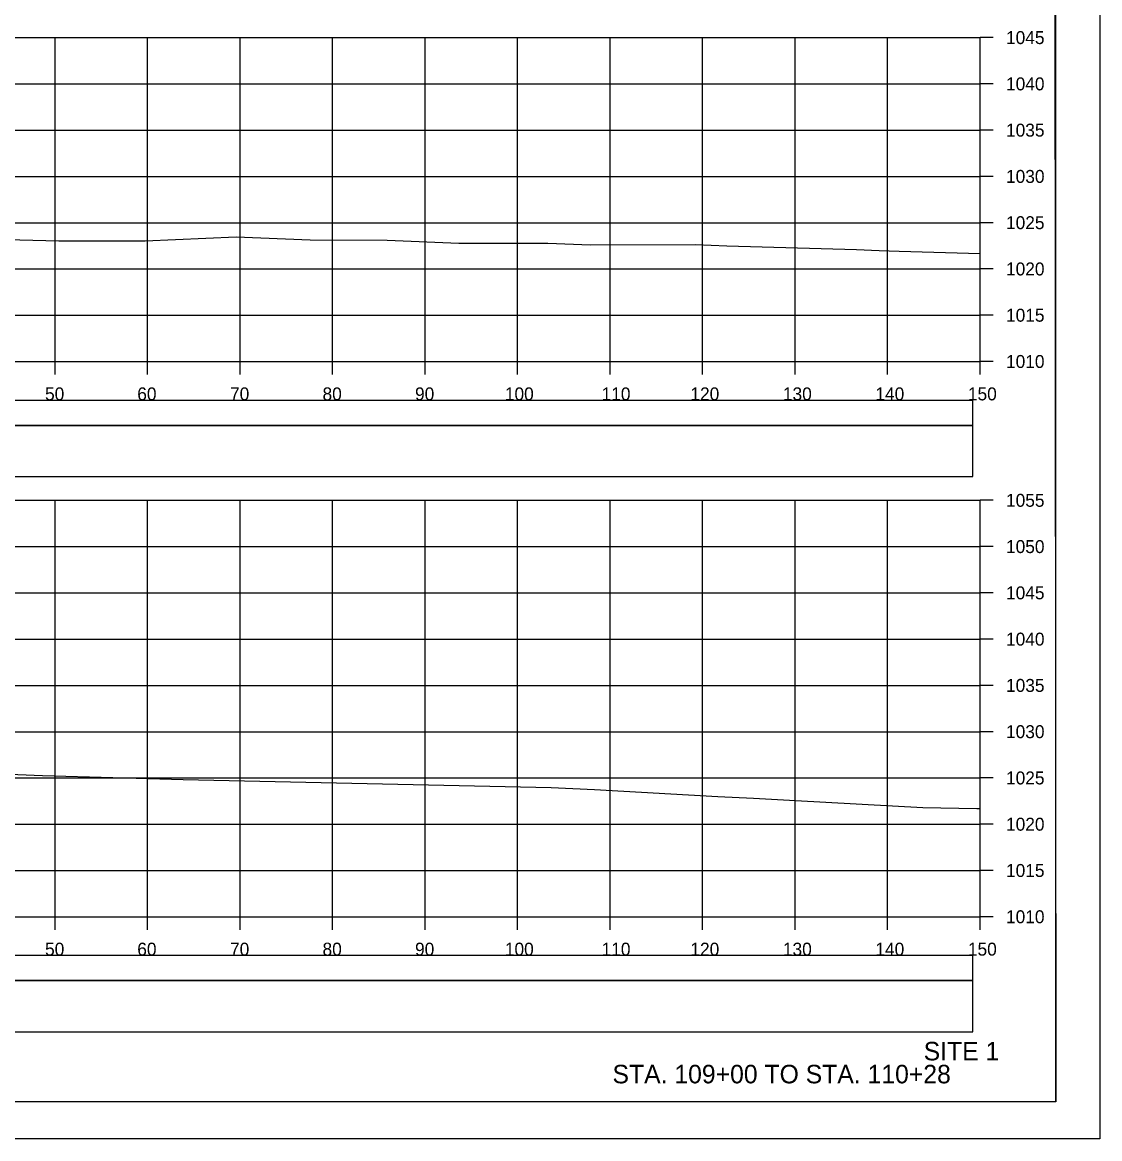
# Model space of a CAD drawing. Extents: x 1370565 to 1374448, y 301010 to 304637.
# Drawn here: x 1370781.5 to 1370898, y 302290.5 to 302411.2 of the extents above; entities that cross this region are included whole.
import ezdxf

# ---------------------------------------------------------------- set-up
doc = ezdxf.new("R2010")
doc.units = 0
for name, color, linetype in [('R_Axis', 7, 'Continuous'), ('R_Axis Annot', 7, 'Continuous'), ('R_Border', 7, 'Continuous'), ('R_Draft', 7, 'Continuous'), ('R_Drive', 7, 'Continuous'), ('R_Exist Surface', 7, 'Continuous'), ('R_Grid', 7, 'Continuous'), ('R_No Plot', 7, 'Continuous')]:
    doc.layers.add(name, color=color, linetype=linetype)

msp = doc.modelspace()

# ---------------------------------------------------------------- linework, layer by layer
at = {"layer": 'R_Axis'}
for p, q in [((1370885.03, 302374.5), (1370885.03, 302409.5)), ((1370886.43, 302409.5), (1370885.03, 302409.5)), ((1370886.43, 302404.5), (1370885.03, 302404.5)), ((1370886.43, 302399.5), (1370885.03, 302399.5)), ((1370886.43, 302394.5), (1370885.03, 302394.5)), ((1370886.43, 302389.5), (1370885.03, 302389.5)), ((1370886.43, 302384.5), (1370885.03, 302384.5)), ((1370886.43, 302379.5), (1370885.03, 302379.5)), ((1370585.03, 302374.5), (1370885.03, 302374.5)), ((1370785.03, 302373.1), (1370785.03, 302374.5)), ((1370795.03, 302373.1), (1370795.03, 302374.5)), ((1370805.03, 302373.1), (1370805.03, 302374.5)), ((1370815.03, 302373.1), (1370815.03, 302374.5)), ((1370825.03, 302373.1), (1370825.03, 302374.5)), ((1370835.03, 302373.1), (1370835.03, 302374.5)), ((1370845.03, 302373.1), (1370845.03, 302374.5)), ((1370855.03, 302373.1), (1370855.03, 302374.5)), ((1370865.03, 302373.1), (1370865.03, 302374.5)), ((1370875.03, 302373.1), (1370875.03, 302374.5)), ((1370885.03, 302373.1), (1370885.03, 302374.5)), ((1370886.43, 302374.5), (1370885.03, 302374.5)), ((1370885.03, 302314.5), (1370885.03, 302359.5)), ((1370886.43, 302359.5), (1370885.03, 302359.5)), ((1370886.43, 302354.5), (1370885.03, 302354.5)), ((1370886.43, 302349.5), (1370885.03, 302349.5)), ((1370886.43, 302344.5), (1370885.03, 302344.5)), ((1370886.43, 302339.5), (1370885.03, 302339.5)), ((1370886.43, 302334.5), (1370885.03, 302334.5)), ((1370886.43, 302329.5), (1370885.03, 302329.5)), ((1370886.43, 302324.5), (1370885.03, 302324.5)), ((1370886.43, 302319.5), (1370885.03, 302319.5)), ((1370585.03, 302314.5), (1370885.03, 302314.5)), ((1370785.03, 302313.1), (1370785.03, 302314.5)), ((1370795.03, 302313.1), (1370795.03, 302314.5)), ((1370805.03, 302313.1), (1370805.03, 302314.5)), ((1370815.03, 302313.1), (1370815.03, 302314.5)), ((1370825.03, 302313.1), (1370825.03, 302314.5)), ((1370835.03, 302313.1), (1370835.03, 302314.5)), ((1370845.03, 302313.1), (1370845.03, 302314.5)), ((1370855.03, 302313.1), (1370855.03, 302314.5)), ((1370865.03, 302313.1), (1370865.03, 302314.5)), ((1370875.03, 302313.1), (1370875.03, 302314.5)), ((1370885.03, 302313.1), (1370885.03, 302314.5)), ((1370886.43, 302314.5), (1370885.03, 302314.5))]:
    msp.add_line(p, q, dxfattribs=at)
at = {"layer": 'R_Border'}
for q in [(1370893.21, 302499.96), (1370577.03, 302294.5)]:
    msp.add_line((1370893.21, 302294.5), q, dxfattribs=at)
at = {"layer": 'R_Drive'}
for points in [[(1370585.82, 302367.6), (1370884.24, 302367.6), (1370884.24, 302370.3), (1370585.82, 302370.3)], [(1370585.82, 302362.08), (1370884.24, 302362.08), (1370884.24, 302367.6), (1370585.82, 302367.6)], [(1370585.82, 302307.6), (1370884.24, 302307.6), (1370884.24, 302310.3), (1370585.82, 302310.3)], [(1370585.82, 302302.08), (1370884.24, 302302.08), (1370884.24, 302307.6), (1370585.82, 302307.6)]]:
    msp.add_lwpolyline(points, close=True, dxfattribs=at)
at = {"layer": 'R_Exist Surface'}
for points in [[(1370733.6, 302388.88), (1370785.42, 302387.55), (1370794.78, 302387.53), (1370804.59, 302387.97), (1370812.6, 302387.65), (1370820.92, 302387.62), (1370828.66, 302387.28), (1370838.3, 302387.29), (1370842.92, 302387.09), (1370854.26, 302387.14), (1370857.65, 302387.01), (1370871.67, 302386.6), (1370874.11, 302386.5), (1370876.28, 302386.42), (1370885.03, 302386.17)], [(1370751.64, 302331.07), (1370783.68, 302329.77), (1370798.89, 302329.33), (1370838.67, 302328.48), (1370843.33, 302328.24), (1370856.69, 302327.51), (1370860.55, 302327.31), (1370865.06, 302327.08), (1370878.85, 302326.31), (1370884.67, 302326.2), (1370885.03, 302326.2)]]:
    msp.add_lwpolyline(points, dxfattribs=at)
at = {"layer": 'R_Grid'}
for p, q in [((1370585.03, 302409.5), (1370885.03, 302409.5)), ((1370785.03, 302374.5), (1370785.03, 302409.5)), ((1370795.03, 302374.5), (1370795.03, 302409.5)), ((1370805.03, 302374.5), (1370805.03, 302409.5)), ((1370815.03, 302374.5), (1370815.03, 302409.5)), ((1370825.03, 302374.5), (1370825.03, 302409.5)), ((1370835.03, 302374.5), (1370835.03, 302409.5)), ((1370845.03, 302374.5), (1370845.03, 302409.5)), ((1370855.03, 302374.5), (1370855.03, 302409.5)), ((1370865.03, 302374.5), (1370865.03, 302409.5)), ((1370875.03, 302374.5), (1370875.03, 302409.5)), ((1370885.03, 302374.5), (1370885.03, 302409.5)), ((1370585.03, 302404.5), (1370885.03, 302404.5)), ((1370585.03, 302399.5), (1370885.03, 302399.5)), ((1370585.03, 302394.5), (1370885.03, 302394.5)), ((1370585.03, 302389.5), (1370885.03, 302389.5)), ((1370585.03, 302384.5), (1370885.03, 302384.5)), ((1370585.03, 302379.5), (1370885.03, 302379.5)), ((1370585.03, 302374.5), (1370885.03, 302374.5)), ((1370585.03, 302359.5), (1370885.03, 302359.5)), ((1370785.03, 302314.5), (1370785.03, 302359.5)), ((1370795.03, 302314.5), (1370795.03, 302359.5)), ((1370805.03, 302314.5), (1370805.03, 302359.5)), ((1370815.03, 302314.5), (1370815.03, 302359.5)), ((1370825.03, 302314.5), (1370825.03, 302359.5)), ((1370835.03, 302314.5), (1370835.03, 302359.5)), ((1370845.03, 302314.5), (1370845.03, 302359.5)), ((1370855.03, 302314.5), (1370855.03, 302359.5)), ((1370865.03, 302314.5), (1370865.03, 302359.5)), ((1370875.03, 302314.5), (1370875.03, 302359.5)), ((1370885.03, 302314.5), (1370885.03, 302359.5)), ((1370585.03, 302354.5), (1370885.03, 302354.5)), ((1370585.03, 302349.5), (1370885.03, 302349.5)), ((1370585.03, 302344.5), (1370885.03, 302344.5)), ((1370585.03, 302339.5), (1370885.03, 302339.5)), ((1370585.03, 302334.5), (1370885.03, 302334.5)), ((1370585.03, 302329.5), (1370885.03, 302329.5)), ((1370585.03, 302324.5), (1370885.03, 302324.5)), ((1370585.03, 302319.5), (1370885.03, 302319.5)), ((1370585.03, 302314.5), (1370885.03, 302314.5))]:
    msp.add_line(p, q, dxfattribs=at)
at = {"layer": 'R_No Plot'}
msp.add_line((1370564.63, 302290.53), (1370897.96, 302290.53), dxfattribs=at)
for points in [[(1370564.62, 302503.86), (1370897.96, 302503.86), (1370897.96, 302290.52), (1370564.62, 302290.52)], [(1370810.95, 302499.96), (1370830.57, 302499.96), (1370830.57, 302490.08), (1370846.68, 302490.08), (1370869.88, 302490.08), (1370869.88, 302457.41), (1370893.09, 302457.41), (1370893.21, 302294.5), (1370577.03, 302294.5), (1370577.03, 302499.96)]]:
    msp.add_lwpolyline(points, close=True, dxfattribs=at)

# ---------------------------------------------------------------- texts
at = {"layer": 'R_Axis Annot'}
for s, p in [('1045', (1370887.83, 302408.8)), ('1040', (1370887.83, 302403.8)), ('1035', (1370887.83, 302398.8)), ('1030', (1370887.83, 302393.8)), ('1025', (1370887.83, 302388.8)), ('1020', (1370887.83, 302383.8)), ('1015', (1370887.83, 302378.8)), ('1010', (1370887.83, 302373.8)), ('50', (1370783.94, 302370.3)), ('60', (1370793.91, 302370.3)), ('70', (1370803.94, 302370.3)), ('80', (1370813.94, 302370.3)), ('90', (1370823.94, 302370.3)), ('100', (1370833.65, 302370.3)), ('110', (1370844.11, 302370.3)), ('120', (1370853.71, 302370.3)), ('130', (1370863.71, 302370.3)), ('140', (1370873.71, 302370.3)), ('150', (1370883.71, 302370.3)), ('1055', (1370887.83, 302358.8)), ('1050', (1370887.83, 302353.8)), ('1045', (1370887.83, 302348.8)), ('1040', (1370887.83, 302343.8)), ('1035', (1370887.83, 302338.8)), ('1030', (1370887.83, 302333.8)), ('1025', (1370887.83, 302328.8)), ('1020', (1370887.83, 302323.8)), ('1015', (1370887.83, 302318.8)), ('1010', (1370887.83, 302313.8)), ('50', (1370783.94, 302310.3)), ('60', (1370793.91, 302310.3)), ('70', (1370803.94, 302310.3)), ('80', (1370813.94, 302310.3)), ('90', (1370823.94, 302310.3)), ('100', (1370833.65, 302310.3)), ('110', (1370844.11, 302310.3)), ('120', (1370853.71, 302310.3)), ('130', (1370863.71, 302310.3)), ('140', (1370873.71, 302310.3)), ('150', (1370883.71, 302310.3))]:
    msp.add_text(s, height=1.4, dxfattribs=at).set_placement(p)
at = {"layer": 'R_Draft'}
for s, p in [('SITE 1', (1370878.93, 302298.98)), ('STA. 109+00 TO STA. 110+28', (1370845.29, 302296.5))]:
    msp.add_text(s, height=2, dxfattribs=at).set_placement(p)

doc.saveas('drawing.dxf')
